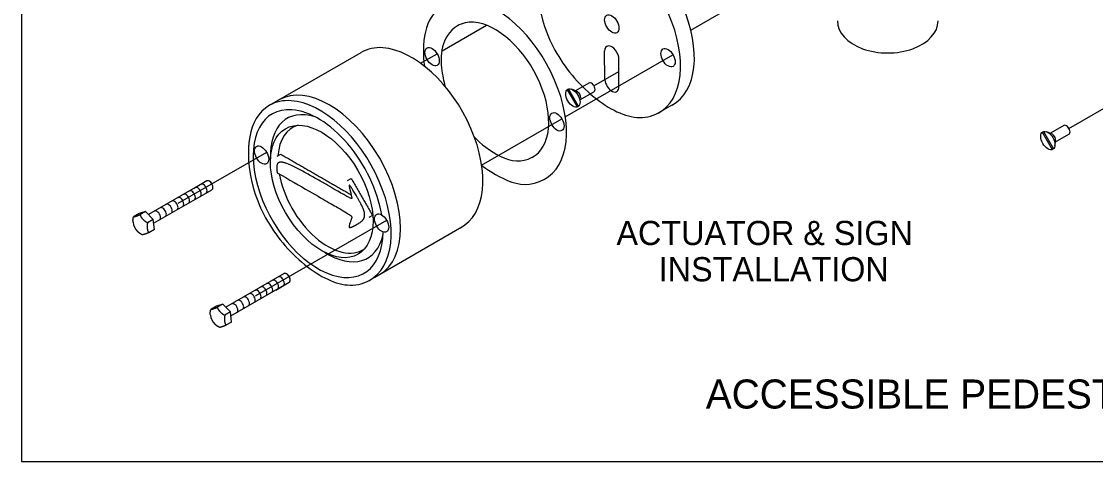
# Model space of a CAD drawing. Extents: x 2815109 to 2818234, y 992846 to 994883.
# Drawn here: x 2815109 to 2816189, y 992846 to 993288 of the extents above; entities that cross this region are included whole.
import ezdxf

# ---------------------------------------------------------------- set-up
doc = ezdxf.new("R2010")
doc.units = 0
for name, color, linetype in [('Common-Notes', 7, 'Continuous'), ('Default', 7, 'Continuous'), ('Draft_Named_Boundary', 7, 'Continuous'), ('Level 16', 7, 'Continuous'), ('Level 31', 7, 'Continuous'), ('Level 33', 7, 'Continuous'), ('Level 34', 7, 'Continuous'), ('Level 35', 7, 'Continuous'), ('Level 36', 7, 'Continuous'), ('Level 38', 7, 'Continuous'), ('Level 41', 7, 'Continuous')]:
    doc.layers.add(name, color=color, linetype=linetype)

msp = doc.modelspace()

# ---------------------------------------------------------------- linework, layer by layer
at = {"layer": 'Draft_Named_Boundary'}
msp.add_lwpolyline([(2815109.5, 992846), (2818234.5, 992846), (2818234.5, 994883.5), (2815109.5, 994883.5)], close=True, dxfattribs=at)
at = {"layer": 'Level 16'}
for p, q in [((2815782, 993279.4), (2815950.9, 993376.9)), ((2815532.2, 993258.5), (2815576.7, 993284.2)), ((2815510.6, 993246), (2815527.2, 993255.6)), ((2815656, 993192.1), (2815764.2, 993254.6)), ((2815684.8, 993223.3), (2815709.8, 993237.7)), ((2816162.1, 993180.6), (2816226.3, 993217.7)), ((2815571.9, 993143.5), (2815652.6, 993190.1)), ((2815267.1, 993105.4), (2815355.9, 993156.7)), ((2815344.7, 993012.4), (2815476.5, 993088.4))]:
    msp.add_line(p, q, dxfattribs=at)
at = {"layer": 'Level 31'}
msp.add_ellipse((2815980, 993288.5), major_axis=(50.6, 0), ratio=0.635085, start_param=3.14158, end_param=6.283185, dxfattribs=at)
at = {"layer": 'Level 33'}
for p, q in [((2815358.8, 993203.8), (2815450.8, 993257)), ((2815695.6, 993229.5), (2815695.5, 993258.4)), ((2815709.8, 993221.9), (2815709.8, 993249.8)), ((2815763.6, 993204.3), (2815749.7, 993196.2)), ((2815295.7, 993127.8), (2815282.2, 993120)), ((2815287.3, 993111.2), (2815300.8, 993119)), ((2815464.7, 993031.2), (2815552.1, 993081.6)), ((2815373.4, 993034.8), (2815359.9, 993027)), ((2815460, 993028.5), (2815469.4, 993033.9)), ((2815365, 993018.2), (2815378.5, 993026))]:
    msp.add_line(p, q, dxfattribs=at)
for centre, major_axis, start_param, end_param in [((2815714.1, 993292.6), (50.6, -87.7), 6.254516, 9.055069), ((2815700.2, 993284.5), (50.6, -87.7), 6.254516, 9.055069), ((2815585.6, 993217.9), (50.6, -87.7), 6.254516, 9.055069), ((2815585.6, 993217.9), (38, -65.8), 2.771884, 3.141593), ((2815585.6, 993217.9), (38, -65.8), 6.254516, 9.055069), ((2815501.5, 993169.3), (50.6, -87.7), 2.771884, 3.141593), ((2815501.5, 993169.3), (50.6, -87.7), 6.254516, 9.055069), ((2815522.1, 993252.7), (-5.06, 8.77), 0, 6.283185), ((2815522.1, 993252.7), (-5.06, 8.77), 4.712389, 4.71239), ((2815702.7, 993254.2), (-5.06, 8.77), 3.893799, 7.078499), ((2815702.7, 993226.4), (-5.06, 8.77), 0.909508, 3.971883), ((2815418.8, 993121.5), (-50.6, 87.7), 3.141593, 6.283185), ((2815407.6, 993115.1), (46.2, -80), 2.770312, 7.057066), ((2815409.4, 993116.1), (50.6, -87.7), 2.771884, 3.141593), ((2815409.4, 993116.1), (50.6, -87.7), 6.254516, 9.055069), ((2815407.6, 993115.1), (46.2, -80), 0.992096, 2.770312), ((2815298.3, 993123.4), (2.53, -4.38), 6.28318, 9.424778), ((2815298.3, 993123.4), (2.53, -4.38), 3.141593, 3.141605), ((2815375.9, 993030.4), (2.53, -4.38), 6.28318, 9.424778), ((2815375.9, 993030.4), (2.53, -4.38), 3.141593, 3.141605)]:
    msp.add_ellipse(centre, major_axis=major_axis, ratio=0.57735, start_param=start_param, end_param=end_param, dxfattribs=at)
for centre in [(2815702.7, 993285.5), (2815759.2, 993251.6), (2815647.6, 993187.2), (2815350.8, 993153.8), (2815471.4, 993085.5)]:
    msp.add_ellipse(centre, major_axis=(-5.06, 8.77), ratio=0.57735, dxfattribs=at)
for points in [[(2815649.5, 993372.2), (2815637.9, 993365), (2815626.3, 993344.3), (2815628.8, 993289.9), (2815656.9, 993234.7), (2815705.7, 993192.9), (2815735.5, 993188.7), (2815749.7, 993196.2)], [(2815535, 993305.5), (2815523.3, 993298.3), (2815512.7, 993279.4), (2815513, 993253), (2815514.4, 993243.2)], [(2815547.6, 993283.6), (2815538.9, 993278.2), (2815530.2, 993262.7), (2815531.3, 993237.7), (2815534.5, 993225.3), (2815535.4, 993222.5)], [(2815358.8, 993203.8), (2815347.1, 993196.6), (2815335.5, 993175.9), (2815338.1, 993121.5), (2815366.1, 993066.3), (2815415, 993024.5), (2815444.7, 993020.3), (2815458.9, 993027.8)], [(2815564.6, 993171.9), (2815570.5, 993165.6), (2815591, 993148.9), (2815612.1, 993146), (2815622.7, 993151.6)], [(2815571.9, 993143.5), (2815575.4, 993140.7), (2815597.9, 993125.3), (2815620.9, 993122), (2815635.1, 993129.5)]]:
    msp.add_open_spline(points, degree=3, dxfattribs=at)
at = {"layer": 'Level 34'}
for start_param, end_param in [(2.573627, 3.978331), (5.446447, 6.851151)]:
    msp.add_ellipse((2815416.9, 993120.5), major_axis=(40.5, -70.1), ratio=0.57735, start_param=start_param, end_param=end_param, dxfattribs=at)
msp.add_ellipse((2815411.2, 993117.2), major_axis=(36.5, -63.1), ratio=0.57735, dxfattribs=at)
msp.add_ellipse((2815411.2, 993117.2), major_axis=(36.5, -63.1), ratio=0.57735, dxfattribs=at)
at = {"layer": 'Level 35'}
for p, q in [((2815366.4, 993152.7), (2815370, 993154.7)), ((2815437.2, 993128.3), (2815440.8, 993130.4)), ((2815462.3, 993093.2), (2815458.7, 993091.1))]:
    msp.add_line(p, q, dxfattribs=at)
for points, degree in [([(2815366.4, 993136.1), (2815365.3, 993145.1), (2815366.4, 993152.7), (2815402.9, 993131.6), (2815439.5, 993110.5), (2815442, 993109.1), (2815441.2, 993112.2), (2815439.2, 993120.3), (2815437.2, 993128.3), (2815447.9, 993109.7), (2815458.7, 993091.1), (2815447.9, 993084.9), (2815437.2, 993078.7), (2815439.2, 993084.5), (2815441.2, 993090.3), (2815442, 993092.5), (2815439.5, 993094), (2815402.9, 993115.1), (2815366.4, 993136.1)], 4), ([(2815370, 993154.7), (2815405.4, 993134.3), (2815440.8, 993113.9)], 2), ([(2815440.8, 993130.4), (2815451.5, 993111.8), (2815462.3, 993093.2)], 2)]:
    msp.add_open_spline(points, degree=degree, dxfattribs=at)
at = {"layer": 'Level 36'}
for start_param, end_param in [(2.991971, 3.85234), (4.156158, 6.332503)]:
    msp.add_ellipse((2815417.2, 993120), major_axis=(35.4, -61.4), ratio=0.57735, start_param=start_param, end_param=end_param, dxfattribs=at)
at = {"layer": 'Level 38'}
for p, q in [((2815295.7, 993127.8), (2815237.2, 993094)), ((2815242.3, 993085.3), (2815300.8, 993119)), ((2815227.7, 993095.1), (2815222, 993091.8)), ((2815234.2, 993097.2), (2815227.7, 993095.1)), ((2815234.2, 993097.2), (2815228.5, 993093.9)), ((2815241.9, 993089.2), (2815234.2, 993097.2)), ((2815241.9, 993089.2), (2815236.2, 993085.9)), ((2815243, 993079.1), (2815241.9, 993089.2)), ((2815243, 993079.1), (2815237.3, 993075.8)), ((2815373.4, 993034.8), (2815314.9, 993001)), ((2815320, 992992.2), (2815378.5, 993026)), ((2815305.4, 993002.1), (2815299.7, 992998.8)), ((2815311.9, 993004.2), (2815305.4, 993002.1)), ((2815311.9, 993004.2), (2815306.2, 993000.9)), ((2815319.5, 992996.2), (2815311.9, 993004.2)), ((2815319.5, 992996.2), (2815313.9, 992992.9)), ((2815320.7, 992986.1), (2815319.5, 992996.2)), ((2815320.7, 992986.1), (2815315, 992982.8))]:
    msp.add_line(p, q, dxfattribs=at)
for centre, major_axis, start_param, end_param in [((2815292.4, 993120), (2.53, -4.38), 6.28318, 9.424778), ((2815292.4, 993120), (2.53, -4.38), 3.141593, 3.141605), ((2815295.3, 993121.7), (2.53, -4.38), 3.141593, 3.141605), ((2815298.3, 993123.4), (-2.53, 4.38), 3.141591, 6.283173), ((2815298.3, 993123.4), (-2.53, 4.38), 6.283173, 6.283185), ((2815274.9, 993109.9), (2.53, -4.38), 6.28318, 9.424778), ((2815274.9, 993109.9), (2.53, -4.38), 3.141593, 3.141605), ((2815277.8, 993111.6), (2.53, -4.38), 3.141593, 3.141605), ((2815280.7, 993113.3), (2.53, -4.38), 6.28318, 9.424778), ((2815280.7, 993113.3), (2.53, -4.38), 3.141593, 3.141605), ((2815283.7, 993115), (2.53, -4.38), 3.141593, 3.141605), ((2815286.6, 993116.7), (2.53, -4.38), 6.28318, 9.424778), ((2815286.6, 993116.7), (2.53, -4.38), 3.141593, 3.141605), ((2815289.5, 993118.4), (2.53, -4.38), 3.141593, 3.141605), ((2815257.4, 993099.8), (2.53, -4.38), 6.28318, 9.424778), ((2815257.4, 993099.8), (2.53, -4.38), 3.141593, 3.141605), ((2815260.3, 993101.5), (2.53, -4.38), 3.141593, 3.141605), ((2815263.2, 993103.2), (2.53, -4.38), 6.28318, 9.424778), ((2815263.2, 993103.2), (2.53, -4.38), 3.141593, 3.141605), ((2815266.1, 993104.9), (2.53, -4.38), 3.141593, 3.141605), ((2815269, 993106.6), (2.53, -4.38), 6.28318, 9.424778), ((2815269, 993106.6), (2.53, -4.38), 3.141593, 3.141605), ((2815272, 993108.2), (2.53, -4.38), 3.141593, 3.141605), ((2815245.7, 993093.1), (2.53, -4.38), 6.28318, 9.424778), ((2815245.7, 993093.1), (2.53, -4.38), 3.141593, 3.141605), ((2815248.6, 993094.7), (2.53, -4.38), 3.141593, 3.141605), ((2815251.5, 993096.4), (2.53, -4.38), 6.28318, 9.424778), ((2815251.5, 993096.4), (2.53, -4.38), 3.141593, 3.141605), ((2815254.4, 993098.1), (2.53, -4.38), 3.141593, 3.141605), ((2815228.8, 993083.3), (5.06, -8.77), 4.066603, 5.113801), ((2815364.2, 993023.6), (2.53, -4.38), 6.28318, 9.424778), ((2815364.2, 993023.6), (2.53, -4.38), 3.141593, 3.141605), ((2815367.2, 993025.3), (2.53, -4.38), 3.141593, 3.141605), ((2815370.1, 993027), (2.53, -4.38), 6.28318, 9.424778), ((2815370.1, 993027), (2.53, -4.38), 3.141593, 3.141605), ((2815373, 993028.7), (2.53, -4.38), 3.141593, 3.141605), ((2815375.9, 993030.4), (-2.53, 4.38), 3.141591, 6.283173), ((2815375.9, 993030.4), (-2.53, 4.38), 6.283173, 6.283185), ((2815346.7, 993013.5), (2.53, -4.38), 6.28318, 9.424778), ((2815346.7, 993013.5), (2.53, -4.38), 3.141593, 3.141605), ((2815349.6, 993015.2), (2.53, -4.38), 3.141593, 3.141605), ((2815352.6, 993016.9), (2.53, -4.38), 6.28318, 9.424778), ((2815352.6, 993016.9), (2.53, -4.38), 3.141593, 3.141605), ((2815355.5, 993018.6), (2.53, -4.38), 3.141593, 3.141605), ((2815358.4, 993020.3), (2.53, -4.38), 6.28318, 9.424778), ((2815358.4, 993020.3), (2.53, -4.38), 3.141593, 3.141605), ((2815361.3, 993021.9), (2.53, -4.38), 3.141593, 3.141605), ((2815326.3, 993001.7), (2.53, -4.38), 3.141593, 3.141605), ((2815329.2, 993003.4), (2.53, -4.38), 6.28318, 9.424778), ((2815329.2, 993003.4), (2.53, -4.38), 3.141593, 3.141605), ((2815332.1, 993005.1), (2.53, -4.38), 3.141593, 3.141605), ((2815335, 993006.8), (2.53, -4.38), 6.28318, 9.424778), ((2815335, 993006.8), (2.53, -4.38), 3.141593, 3.141605), ((2815337.9, 993008.4), (2.53, -4.38), 3.141593, 3.141605), ((2815340.9, 993010.1), (2.53, -4.38), 6.28318, 9.424778), ((2815340.9, 993010.1), (2.53, -4.38), 3.141593, 3.141605), ((2815343.8, 993011.8), (2.53, -4.38), 3.141593, 3.141605), ((2815323.3, 993000), (2.53, -4.38), 6.28318, 9.424778), ((2815323.3, 993000), (2.53, -4.38), 3.141593, 3.141605), ((2815306.4, 992990.2), (5.06, -8.77), 4.066603, 5.113801)]:
    msp.add_ellipse(centre, major_axis=major_axis, ratio=0.57735, start_param=start_param, end_param=end_param, dxfattribs=at)
for points in [[(2815222, 993091.8), (2815222.5, 993091.8), (2815223.2, 993092), (2815224.3, 993092.4)], [(2815224.3, 993092.4), (2815225.5, 993092.7), (2815226.9, 993093.3), (2815228.5, 993093.9)], [(2815228.5, 993093.9), (2815229.2, 993092.3), (2815230.1, 993090.8), (2815231.4, 993089.4)], [(2815221.7, 993086.2), (2815221.5, 993088), (2815221.6, 993089.9), (2815222, 993091.8)], [(2815231.4, 993089.4), (2815232.8, 993088), (2815234.4, 993086.9), (2815236.2, 993085.9)], [(2815236.2, 993085.9), (2815235.8, 993084), (2815235.6, 993082.1), (2815235.8, 993080.3)], [(2815230.8, 993073.7), (2815229.1, 993074.7), (2815227.4, 993075.8), (2815226.1, 993077.2)], [(2815233.2, 993074.2), (2815232, 993073.9), (2815231.3, 993073.7), (2815230.8, 993073.7)], [(2815237.3, 993075.8), (2815235.8, 993075.2), (2815234.3, 993074.6), (2815233.2, 993074.2)], [(2815235.8, 993080.3), (2815236, 993078.6), (2815236.6, 993077.1), (2815237.3, 993075.8)], [(2815299.3, 992993.2), (2815299.1, 992994.9), (2815299.3, 992996.8), (2815299.7, 992998.8)], [(2815299.7, 992998.8), (2815300.2, 992998.8), (2815300.9, 992998.9), (2815302, 992999.3)], [(2815302, 992999.3), (2815303.1, 992999.7), (2815304.6, 993000.2), (2815306.2, 993000.9)], [(2815306.2, 993000.9), (2815306.9, 992999.3), (2815307.8, 992997.7), (2815309.1, 992996.4)], [(2815309.1, 992996.4), (2815310.4, 992995), (2815312.1, 992993.9), (2815313.9, 992992.9)], [(2815308.5, 992980.7), (2815306.7, 992981.6), (2815305.1, 992982.8), (2815303.7, 992984.1)], [(2815313.9, 992992.9), (2815313.5, 992991), (2815313.3, 992989), (2815313.5, 992987.3)], [(2815313.5, 992987.3), (2815313.7, 992985.6), (2815314.3, 992984.1), (2815315, 992982.8)], [(2815310.8, 992981.2), (2815309.7, 992980.8), (2815309, 992980.7), (2815308.5, 992980.7)], [(2815315, 992982.8), (2815313.4, 992982.1), (2815311.9, 992981.5), (2815310.8, 992981.2)]]:
    msp.add_open_spline(points, degree=2, dxfattribs=at)
at = {"layer": 'Level 41'}
for p, q in [((2815679.7, 993226.2), (2815666.2, 993218.4)), ((2815658, 993219.4), (2815668.1, 993202)), ((2815659.2, 993220.1), (2815669.2, 993202.7)), ((2815667.4, 993217.9), (2815662.5, 993219.9)), ((2815671.3, 993209.6), (2815684.8, 993217.4)), ((2816157, 993183.5), (2816143.5, 993175.7)), ((2816135.3, 993176.8), (2816145.4, 993159.3)), ((2816136.5, 993177.4), (2816146.6, 993160)), ((2816144.7, 993175.3), (2816139.8, 993177.2)), ((2816148, 993163), (2816148.8, 993168.2)), ((2816148.6, 993167), (2816162.1, 993174.8))]:
    msp.add_line(p, q, dxfattribs=at)
for centre in [(2815663.6, 993211.1), (2816140.9, 993168.4)]:
    msp.add_ellipse(centre, major_axis=(-5.06, 8.77), ratio=0.57735, dxfattribs=at)
for centre, start_param, end_param in [((2815682.3, 993221.8), 6.28318, 9.424778), ((2815682.3, 993221.8), 3.141593, 3.141605), ((2815667.9, 993213.5), 0.630137, 2.511455), ((2816159.6, 993179.1), 6.28318, 9.424778), ((2816159.6, 993179.1), 3.141593, 3.141605), ((2816145.2, 993170.9), 0.630137, 2.511455)]:
    msp.add_ellipse(centre, major_axis=(2.53, -4.38), ratio=0.57735, start_param=start_param, end_param=end_param, dxfattribs=at)

# ---------------------------------------------------------------- texts
at = {"layer": 'Common-Notes'}
msp.add_text('ACCESSIBLE PEDESTRIAN SIGNAL ASSEMBLY', height=29.16, dxfattribs=at).set_placement((2815797.2, 992899.2))
at = {"layer": 'Default'}
for s, p in [('ACTUATOR & SIGN', (2815707.4, 993063.4)), ('INSTALLATION', (2815749.9, 993027))]:
    msp.add_text(s, height=24.3, dxfattribs=at).set_placement(p)

doc.saveas('drawing.dxf')
